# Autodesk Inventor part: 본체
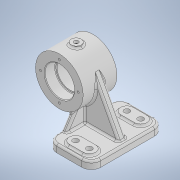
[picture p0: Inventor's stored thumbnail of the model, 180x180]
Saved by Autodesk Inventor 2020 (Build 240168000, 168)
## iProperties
Created: 2023-08
Part Number: 본체
Material: 일반
Document SubType Name: Modeling
Designer: oem
Density: 1 g/cm^3
Appearance: 기본값
Mass: 287.983 g
Surface Area: 537.036 cm^2
Volume: 287.983 cm^3
Author: oem
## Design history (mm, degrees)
sketch "스케치1"
  geometry: C1 r 38 at (0, 0); 1 further point
  constraints: 1 centre point, 1 coincident
  dimensions: "d0" = 76 diameter of C1
extrude "돌출1" new body sketch "스케치1" stored distance "d1" = 54; taper "d2" = 0 deg
node "작업 평면1"
sketch "스케치2"
  geometry: L1 (-38, -27)-(38, -27) reference; L2 (-12, -58)-(-82, -58); L3 (-82, -58)-(-82, 58); L4 (-82, 58)-(-12, 58); L5 (-12, 58)-(-12, -58); L6 (-12, -58)-(-82, 58); L7 (-82, -58)-(-12, 58); 3 further points
  constraints: 12 end point, 3 midpoint, 2 parallel, 1 horizontal, 1 horizontal alignment, 1 perpendicular
  dimensions: "d4" = 116 distance of L2.end L3.end; "d5" = 70 distance of L2.start L2.end; "d6" = 82 distance from line of L3 point (0, 0)
extrude "돌출2" join sketch "스케치2" distance "d7" = 12; taper "d8" = 0 deg
fillet "모깎기1" dims "d9" = 15
sketch "스케치4"
  geometry: 1 further point
sketch "스케치5"
  geometry: L1 (82, -43)-(82, 43) reference; L2 (40, -41)-(62, -41); L3 (40, -51)-(62, -51); L4 (62, -31)-(40, -31); C1 r 4.5 at (40, -41); C2 r 4.5 at (62, -41); A1 r 10 centre (40, -41) between (40, -31) and (40, -51); A2 r 10 centre (62, -41) between (62, -51) and (62, -31); 2 further points
  constraints: 8 end point, 4 centre point, 4 point on circle, 4 tangent, 1 horizontal, 1 horizontal alignment, 1 midpoint, 1 parallel
  dimensions: "d10" = 9 diameter of C1; "d11" = 9 diameter of C2; "d12" = 22 distance of L2.end L2.start; "d13" = 20 distance from line of L1 L2.end; "d14" = 41 vertical distance of L2.end point (0, 0); "d15" = 20 diameter of A2
extrude "돌출3" join sketch "스케치5" distance "d16" = 3; taper "d17" = 0 deg
extrude "돌출4" cut sketch "스케치5" stored distance "d18" = 30; taper "d19" = 0 deg
node "작업 평면2"
sketch "스케치6"
  geometry: L1 (-38, -27)-(38, -27) reference; C1 r 8 at (0, 0); 1 further point
  constraints: 1 centre point, 1 coincident
  dimensions: "d21" = 16 diameter of C1
extrude "돌출5" join sketch "스케치6" stored distance "d22" = 30; taper "d23" = 0 deg
sketch "스케치7"
  geometry: L1 (38, 27)-(-38, 27) reference; L2 (0, 27)-(0, -27); L3 (-38, -27)-(38, -27) reference; L4 (23.5, 27)-(23.5, 10); L5 (23.5, 10)-(20.5, 10); L6 (20.5, 10)-(20.5, -10); L7 (20.5, -10)-(23.5, -10); L8 (23.5, -10)-(23.5, -27); 1 further point
  constraints: 12 end point, 4 point on line, 3 perpendicular, 2 midpoint, 1 collinear, 1 vertical
  dimensions: "d24" = 47 diameter of L4 L2; "d25" = 41 diameter of L6 L2; "d26" = 17 distance of L4.start L4.end
revolve "회전1" sketch "스케치7" stored, may be unused: angle "d27" = 90 deg
sketch "스케치8"
  geometry: C1 r 8 at (0, 0) reference; 2 further points
  constraints: 1 coincident
hole "구멍1" sketch "스케치8" at (0, 0) diameter "d28" = 5.1881; stored, may be unused: countersink angle "d32" = 90 deg, drill point angle "d34" = 0 deg; dims "d29" = 12, "d30" = 7, "d31" = 4, "d33" = 30
sketch "스케치9"
  geometry: C1 r 23.5 at (0, 0) reference; 1 further point
  constraints: 1 vertical alignment
  dimensions: "d35" = 30 distance of C1.centre point (0, 30)
hole "구멍2" sketch "스케치9" at (0, 30) diameter "d36" = 3.45873; stored, may be unused: countersink angle "d40" = 90 deg, drill point angle "d42" = 118 deg; dims "d37" = 8, "d38" = 7, "d39" = 4, "d41" = 10
fillet "모깎기2" dims "d46" = 1
chamfer "모따기1" distance "d47" = 1; stored, may be unused: second distance "d48" = 2, angle "d49" = 45 deg
fillet "모깎기3" dims "d50" = 3
node "작업 평면4"
sketch "스케치17"
  geometry: L1 (7, 12)-(26.815, 42.513); L2 (26.815, 42.513)-(59.185, 42.513); L3 (6.5, 0)-(6.5, 15) reference; L4 (59.185, 42.513)-(79, 12); L5 (86, 12)-(0, 12) reference; L6 (7, 12)-(79, 12); L7 (-15, 12)-(-15, 0) reference; L8 (101, 0)-(101, 12) reference; 1 further point
  constraints: 8 end point, 1 equal length, 1 parallel, 1 perpendicular, 1 point on line
  dimensions: "d78" = 22 distance from line of L7 L1.start; "d79" = 22 distance from line of L8 L4.end; "d80" = 33 deg angle of L7 L1; "d81" = 32.36973 distance of L1.end L2.end
extrude "돌출7" join sketch "스케치17" distance "d82" = 8; taper "d83" = 0 deg
sketch "스케치11"
  geometry: L1 (12, -58)-(27, -58) reference; L2 (67, -58)-(82, -58) reference; L3 (33.529, 17.882)-(74, -58); L4 (82, -58)-(82, -70) reference; L5 (12, -58)-(74, -58); 2 further points
  constraints: 4 end point, 1 collinear, 1 point on line, 3 other
  dimensions: "d51" = 8 distance from line of L4 L3.end
feature "리브1" sketch "스케치11" dims "d57" = 1, "d58" = 12, "d59" = 0, "d60" = 0, "d61" = 1, "d62" = 1
fillet "모깎기10" dims "d69" = 3
node "작업 평면3"
sketch "스케치15"
  geometry: L1 (70, -43)-(70, 43) reference; 3 further points
  constraints: 1 horizontal alignment, 1 midpoint, 1 other
  dimensions: "d71" = 19 distance from line of L1 point (51, 0)
fillet "모깎기11" dims "d84" = 3
fillet "모깎기12" dims "d85" = 3
fillet "모깎기13" dims "d86" = 3
fillet "모깎기14" dims "d87" = 3
fillet "모깎기15" dims "d88" = 3
fillet "모깎기16" dims "d89" = 3
feature "엠보싱1" dims "d0" = 76, "d90" = 0.5, "d91" = 0
node "솔리드1"
mirror "미러1"
pattern_circular "원형 패턴1" dims angle "d44" = 360 deg
mirror "미러2"
feature "A9D066F2-1C7D-4E18-AEED-F7BC21143FA4" dims "d28" = 5.1881, "d29" = 12, "d30" = 7, "d31" = 4, "d32" = 90 deg, "d33" = 30, "d34" = 0
other parameters: "d20" = 41, "d77" = -8
